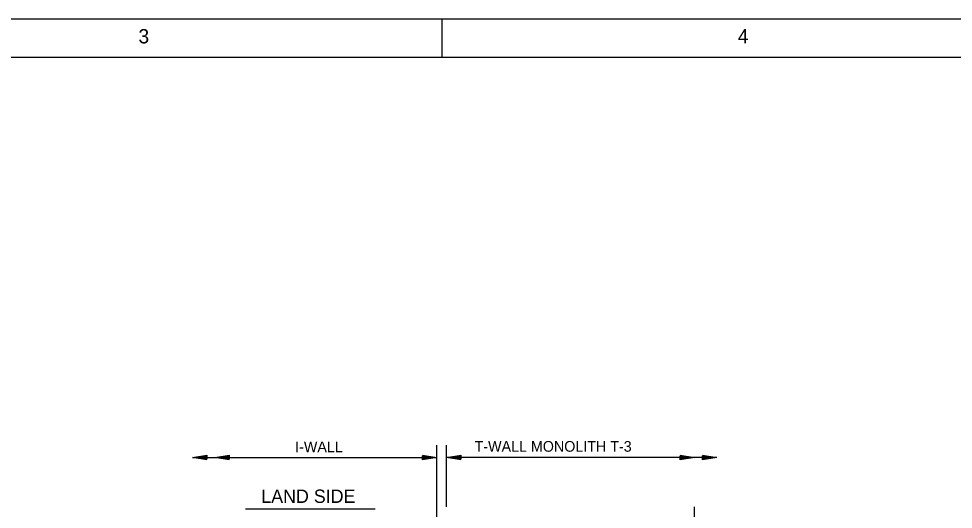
# Model space of a CAD drawing. Extents: x 22369.6 to 22428.3, y 22369.6 to 22415.
# Drawn here: x 22395.6 to 22411.94, y 22406.38 to 22414.96 of the extents above; entities that cross this region are included whole.
import ezdxf

# ---------------------------------------------------------------- set-up
doc = ezdxf.new("R2010")
doc.units = 0
for name, color, linetype in [('Level 1', 7, 'Continuous'), ('Level 10', 7, 'Continuous'), ('Level 2', 7, 'Continuous'), ('Level 3', 7, 'Continuous'), ('Level 8', 7, 'Continuous'), ('Level 9', 7, 'Continuous')]:
    doc.layers.add(name, color=color, linetype=linetype)

msp = doc.modelspace()

# ---------------------------------------------------------------- linework, layer by layer
at = {"layer": 'Level 1'}
for p, q in [((22402.914, 22405.333), (22402.914, 22407.503)), ((22403.08, 22406.427), (22403.08, 22407.503)), ((22398.642, 22407.287), (22402.914, 22407.287)), ((22407.807, 22407.287), (22403.08, 22407.287)), ((22407.414, 22406.427), (22407.414, 22402.983))]:
    msp.add_line(p, q, dxfattribs=at)
msp.add_lwpolyline([(22369.621, 22414.955), (22428.288, 22414.955), (22428.288, 22369.621), (22369.621, 22369.621)], close=True, dxfattribs=at)
at = {"layer": 'Level 10'}
for p, q in [((22403.008, 22414.288), (22403.008, 22414.96)), ((22399.57, 22406.39), (22401.836, 22406.39))]:
    msp.add_line(p, q, dxfattribs=at)
at = {"layer": 'Level 2'}
for points in [[(22398.891, 22407.246), (22398.642, 22407.287), (22398.891, 22407.329), (22398.891, 22407.258), (22398.711, 22407.287), (22398.88, 22407.315), (22398.88, 22407.27), (22398.778, 22407.287), (22398.87, 22407.302), (22398.87, 22407.283), (22398.847, 22407.287)], [(22399.28, 22407.246), (22399.031, 22407.287), (22399.28, 22407.329), (22399.28, 22407.258), (22399.1, 22407.287), (22399.27, 22407.315), (22399.27, 22407.27), (22399.167, 22407.287), (22399.259, 22407.302), (22399.259, 22407.283), (22399.236, 22407.287)], [(22402.664, 22407.329), (22402.914, 22407.287), (22402.664, 22407.246), (22402.664, 22407.317), (22402.844, 22407.287), (22402.675, 22407.259), (22402.675, 22407.305), (22402.778, 22407.287), (22402.686, 22407.273), (22402.686, 22407.291), (22402.708, 22407.287)], [(22403.33, 22407.246), (22403.08, 22407.287), (22403.33, 22407.329), (22403.33, 22407.258), (22403.15, 22407.287), (22403.319, 22407.315), (22403.319, 22407.27), (22403.216, 22407.287), (22403.308, 22407.302), (22403.308, 22407.283), (22403.286, 22407.287)], [(22407.168, 22407.329), (22407.418, 22407.287), (22407.168, 22407.246), (22407.168, 22407.317), (22407.348, 22407.287), (22407.179, 22407.259), (22407.179, 22407.305), (22407.282, 22407.287), (22407.19, 22407.273), (22407.19, 22407.291), (22407.212, 22407.287)], [(22407.558, 22407.329), (22407.807, 22407.287), (22407.558, 22407.246), (22407.558, 22407.317), (22407.738, 22407.287), (22407.568, 22407.259), (22407.568, 22407.305), (22407.671, 22407.287), (22407.579, 22407.273), (22407.579, 22407.291), (22407.602, 22407.287)]]:
    msp.add_lwpolyline(points, dxfattribs=at)
at = {"layer": 'Level 8'}
for p, q in [((22399.27, 22407.315), (22399.27, 22407.315)), ((22399.28, 22407.329), (22399.28, 22407.329)), ((22407.168, 22407.329), (22407.168, 22407.329)), ((22407.168, 22407.317), (22407.168, 22407.317)), ((22407.179, 22407.305), (22407.179, 22407.305)), ((22398.642, 22407.287), (22398.642, 22407.287)), ((22398.711, 22407.287), (22398.711, 22407.287)), ((22399.236, 22407.287), (22399.236, 22407.287)), ((22399.259, 22407.302), (22399.259, 22407.302)), ((22399.259, 22407.283), (22399.259, 22407.283)), ((22399.27, 22407.27), (22399.27, 22407.27)), ((22399.28, 22407.258), (22399.28, 22407.258)), ((22399.28, 22407.246), (22399.28, 22407.246)), ((22402.844, 22407.287), (22402.844, 22407.287)), ((22402.914, 22407.287), (22402.914, 22407.287)), ((22403.08, 22407.287), (22403.08, 22407.287)), ((22403.15, 22407.287), (22403.15, 22407.287)), ((22407.168, 22407.246), (22407.168, 22407.246)), ((22407.179, 22407.259), (22407.179, 22407.259)), ((22407.19, 22407.291), (22407.19, 22407.291)), ((22407.19, 22407.273), (22407.19, 22407.273)), ((22407.212, 22407.287), (22407.212, 22407.287)), ((22407.738, 22407.287), (22407.738, 22407.287)), ((22407.807, 22407.287), (22407.807, 22407.287))]:
    msp.add_line(p, q, dxfattribs=at)
at = {"layer": 'Level 9'}
msp.add_line((22371.621, 22414.288), (22423.952, 22414.288), dxfattribs=at)

# ---------------------------------------------------------------- texts
at = {"layer": 'Level 1'}
for s, p in [('3', (22397.696, 22414.528)), ('4', (22408.176, 22414.528))]:
    msp.add_text(s, height=0.25, dxfattribs=at).set_placement(p)
at = {"layer": 'Level 10'}
msp.add_text('LAND SIDE', height=0.2333, dxfattribs=at).set_placement((22399.843, 22406.494))
at = {"layer": 'Level 3'}
for s, height, p in [('I-WALL', 0.1867, (22400.436, 22407.381)), ('T-WALL MONOLITH T-3', 0.18667, (22403.574, 22407.389))]:
    msp.add_text(s, height=height, dxfattribs=at).set_placement(p)

doc.saveas('drawing.dxf')
